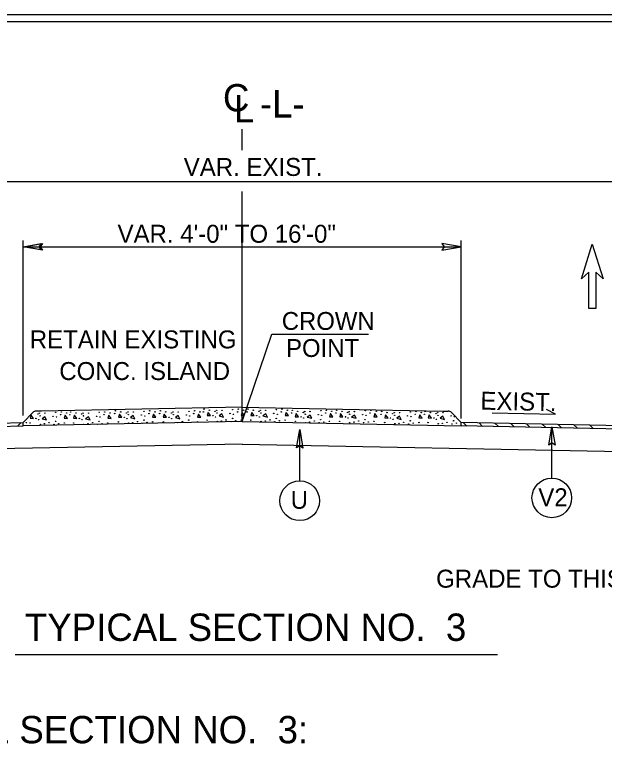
# Model space of a CAD drawing. Extents: x 1901670 to 1902225, y 193498 to 194278.
# Drawn here: x 1902030.87 to 1902052.41, y 194018.9 to 194045.77 of the extents above; entities that cross this region are included whole.
import ezdxf

# ---------------------------------------------------------------- set-up
doc = ezdxf.new("R2010")
doc.units = 0
for name, color, linetype in [('Old_Level_1', 7, 'Continuous'), ('Old_Level_11', 7, 'Continuous'), ('Old_Level_2', 7, 'Continuous'), ('Old_Level_20', 7, 'Continuous'), ('Prop Dimension', 7, 'Continuous'), ('Sheet Border Standard 30in CELL', 7, 'Continuous'), ('Sheet Plot Border Inside CELL', 7, 'Continuous'), ('Typical Terminator CELL', 7, 'Continuous'), ('Typical Text Grade Point CELL', 7, 'Continuous')]:
    doc.layers.add(name, color=color, linetype=linetype)

# ---------------------------------------------------------------- blocks, each defined once
blk = doc.blocks.new('TERMINATOR')
at = {"layer": 'Typical Terminator CELL'}
blk.add_lwpolyline([(-0.469, 0.081), (0, 0), (-0.471, -0.083), (-0.411, 0)], close=True, dxfattribs=at)

msp = doc.modelspace()

# ---------------------------------------------------------------- linework, layer by layer
at = {"layer": 'Old_Level_1'}
for p, q in [((1902039.184, 194040.822), (1902039.184, 194041.59)), ((1902039.184, 194030.906), (1902039.184, 194039.306)), ((1902039.184, 194031.434), (1902031.851, 194031.288)), ((1902039.184, 194031.434), (1902046.517, 194031.288)), ((1902031.184, 194030.871), (1902031.537, 194031.237)), ((1902031.471, 194031.137), (1902031.437, 194031.024)), ((1902031.557, 194031.017), (1902031.471, 194031.137)), ((1902031.851, 194031.288), (1902031.657, 194031.288)), ((1902032.72, 194031.137), (1902032.686, 194031.024)), ((1902032.807, 194031.017), (1902032.72, 194031.137)), ((1902033.06, 194031.137), (1902033.025, 194031.024)), ((1902033.145, 194031.017), (1902033.06, 194031.137)), ((1902034.308, 194031.137), (1902034.274, 194031.024)), ((1902034.395, 194031.017), (1902034.308, 194031.137)), ((1902034.699, 194031.18), (1902034.665, 194031.066)), ((1902034.784, 194031.06), (1902034.699, 194031.18)), ((1902035.206, 194031.124), (1902035.103, 194031.049)), ((1902035.269, 194031.009), (1902035.206, 194031.124)), ((1902035.948, 194031.18), (1902035.913, 194031.066)), ((1902036.034, 194031.06), (1902035.948, 194031.18)), ((1902036.339, 194031.18), (1902036.304, 194031.066)), ((1902036.424, 194031.06), (1902036.339, 194031.18)), ((1902036.846, 194031.124), (1902036.743, 194031.049)), ((1902036.909, 194031.009), (1902036.846, 194031.124)), ((1902037.588, 194031.18), (1902037.553, 194031.066)), ((1902037.674, 194031.06), (1902037.588, 194031.18)), ((1902037.937, 194031.241), (1902037.903, 194031.127)), ((1902037.903, 194031.127), (1902038.023, 194031.121)), ((1902038.023, 194031.121), (1902037.937, 194031.241)), ((1902038.445, 194031.185), (1902038.342, 194031.11)), ((1902038.507, 194031.07), (1902038.445, 194031.185)), ((1902039.186, 194031.241), (1902039.152, 194031.127)), ((1902039.152, 194031.127), (1902039.273, 194031.121)), ((1902039.273, 194031.121), (1902039.186, 194031.241)), ((1902039.537, 194031.241), (1902039.503, 194031.127)), ((1902039.503, 194031.127), (1902039.623, 194031.121)), ((1902039.623, 194031.121), (1902039.537, 194031.241)), ((1902040.044, 194031.185), (1902039.941, 194031.11)), ((1902040.107, 194031.07), (1902040.044, 194031.185)), ((1902040.786, 194031.241), (1902040.752, 194031.127)), ((1902040.752, 194031.127), (1902040.872, 194031.121)), ((1902040.872, 194031.121), (1902040.786, 194031.241)), ((1902041.159, 194031.198), (1902041.124, 194031.084)), ((1902041.244, 194031.078), (1902041.159, 194031.198)), ((1902041.666, 194031.141), (1902041.563, 194031.066)), ((1902041.729, 194031.027), (1902041.666, 194031.141)), ((1902042.408, 194031.198), (1902042.373, 194031.084)), ((1902042.494, 194031.078), (1902042.408, 194031.198)), ((1902042.781, 194031.198), (1902042.747, 194031.084)), ((1902042.867, 194031.078), (1902042.781, 194031.198)), ((1902043.288, 194031.141), (1902043.185, 194031.066)), ((1902043.351, 194031.027), (1902043.288, 194031.141)), ((1902044.03, 194031.198), (1902043.996, 194031.084)), ((1902044.116, 194031.078), (1902044.03, 194031.198)), ((1902044.427, 194031.155), (1902044.393, 194031.041)), ((1902044.513, 194031.035), (1902044.427, 194031.155)), ((1902045.676, 194031.155), (1902045.642, 194031.041)), ((1902045.763, 194031.035), (1902045.676, 194031.155)), ((1902046.011, 194031.155), (1902045.977, 194031.041)), ((1902046.097, 194031.035), (1902046.011, 194031.155)), ((1902046.517, 194031.288), (1902046.711, 194031.288)), ((1902047.184, 194030.871), (1902046.831, 194031.237)), ((1902048.323, 194031.222), (1902050.638, 194031.173)), ((1902050.638, 194031.173), (1902050.305, 194031.34)), ((1902019.184, 194030.631), (1902031.184, 194030.871)), ((1902030.977, 194030.742), (1902031.105, 194030.869)), ((1902039.184, 194030.906), (1902031.184, 194030.746)), ((1902031.184, 194030.746), (1902031.184, 194030.871)), ((1902031.437, 194031.024), (1902031.557, 194031.017)), ((1902031.979, 194031.081), (1902031.875, 194031.006)), ((1902031.875, 194031.006), (1902032.041, 194030.966)), ((1902032.041, 194030.966), (1902031.979, 194031.081)), ((1902032.686, 194031.024), (1902032.807, 194031.017)), ((1902033.025, 194031.024), (1902033.145, 194031.017)), ((1902033.567, 194031.081), (1902033.464, 194031.006)), ((1902033.464, 194031.006), (1902033.629, 194030.966)), ((1902033.629, 194030.966), (1902033.567, 194031.081)), ((1902034.274, 194031.024), (1902034.395, 194031.017)), ((1902034.665, 194031.066), (1902034.784, 194031.06)), ((1902035.103, 194031.049), (1902035.269, 194031.009)), ((1902035.913, 194031.066), (1902036.034, 194031.06)), ((1902036.304, 194031.066), (1902036.424, 194031.06)), ((1902036.743, 194031.049), (1902036.909, 194031.009)), ((1902037.553, 194031.066), (1902037.674, 194031.06)), ((1902038.342, 194031.11), (1902038.507, 194031.07)), ((1902039.184, 194030.906), (1902047.184, 194030.746)), ((1902039.941, 194031.11), (1902040.107, 194031.07)), ((1902041.124, 194031.084), (1902041.244, 194031.078)), ((1902041.563, 194031.066), (1902041.729, 194031.027)), ((1902042.373, 194031.084), (1902042.494, 194031.078)), ((1902042.747, 194031.084), (1902042.867, 194031.078)), ((1902043.185, 194031.066), (1902043.351, 194031.027)), ((1902043.996, 194031.084), (1902044.116, 194031.078)), ((1902044.393, 194031.041), (1902044.513, 194031.035)), ((1902044.935, 194031.099), (1902044.832, 194031.024)), ((1902044.832, 194031.024), (1902044.997, 194030.984)), ((1902044.997, 194030.984), (1902044.935, 194031.099)), ((1902045.642, 194031.041), (1902045.763, 194031.035)), ((1902045.977, 194031.041), (1902046.097, 194031.035)), ((1902046.519, 194031.099), (1902046.415, 194031.024)), ((1902046.415, 194031.024), (1902046.581, 194030.984)), ((1902046.581, 194030.984), (1902046.519, 194031.099)), ((1902047.184, 194030.746), (1902047.184, 194030.871)), ((1902058.184, 194030.651), (1902047.184, 194030.871)), ((1902047.391, 194030.742), (1902047.264, 194030.869)), ((1902047.968, 194030.73), (1902047.841, 194030.858)), ((1902019.184, 194030.506), (1902031.184, 194030.746)), ((1902057.184, 194030.546), (1902047.184, 194030.746)), ((1902048.546, 194030.719), (1902048.418, 194030.846)), ((1902049.123, 194030.707), (1902048.995, 194030.835)), ((1902049.7, 194030.696), (1902049.572, 194030.823)), ((1902050.277, 194030.684), (1902050.15, 194030.812)), ((1902050.854, 194030.673), (1902050.727, 194030.8)), ((1902051.432, 194030.661), (1902051.304, 194030.789)), ((1902052.009, 194030.649), (1902051.881, 194030.777)), ((1902039.184, 194030.083), (1902015.762, 194029.615)), ((1902039.184, 194030.083), (1902057.184, 194029.723))]:
    msp.add_line(p, q, dxfattribs=at)
for centre in [(1902031.728, 194031.178), (1902031.784, 194031.212), (1902031.801, 194031.115), (1902031.978, 194031.212), (1902032.372, 194031.241), (1902032.549, 194031.155), (1902032.578, 194031.257), (1902032.772, 194031.218), (1902032.888, 194031.155), (1902032.917, 194031.257), (1902033.111, 194031.218), (1902033.316, 194031.178), (1902033.372, 194031.212), (1902033.389, 194031.115), (1902033.566, 194031.212), (1902033.96, 194031.241), (1902034.137, 194031.155), (1902034.166, 194031.257), (1902034.36, 194031.218), (1902034.528, 194031.198), (1902034.556, 194031.299), (1902034.75, 194031.26), (1902034.956, 194031.221), (1902035.012, 194031.255), (1902035.029, 194031.158), (1902035.206, 194031.255), (1902035.503, 194031.141), (1902035.6, 194031.283), (1902035.777, 194031.198), (1902035.805, 194031.299), (1902035.999, 194031.26), (1902036.168, 194031.198), (1902036.196, 194031.299), (1902036.39, 194031.26), (1902036.596, 194031.221), (1902036.652, 194031.255), (1902036.669, 194031.158), (1902036.846, 194031.255), (1902037.143, 194031.141), (1902037.24, 194031.283), (1902037.417, 194031.198), (1902037.445, 194031.299), (1902037.639, 194031.26), (1902037.766, 194031.259), (1902037.795, 194031.36), (1902037.989, 194031.321), (1902038.114, 194031.122), (1902038.194, 194031.281), (1902038.25, 194031.316), (1902038.267, 194031.219), (1902038.444, 194031.316), (1902038.741, 194031.201), (1902038.838, 194031.344), (1902038.867, 194031.173), (1902039.015, 194031.259), (1902039.044, 194031.36), (1902039.238, 194031.321), (1902039.366, 194031.259), (1902039.394, 194031.36), (1902039.589, 194031.321), (1902039.714, 194031.122), (1902039.794, 194031.281), (1902039.85, 194031.316), (1902039.867, 194031.219), (1902040.044, 194031.316), (1902040.341, 194031.201), (1902040.438, 194031.344), (1902040.466, 194031.173), (1902040.615, 194031.259), (1902040.643, 194031.36), (1902040.838, 194031.321), (1902040.988, 194031.215), (1902041.016, 194031.317), (1902041.21, 194031.278), (1902041.416, 194031.238), (1902041.472, 194031.272), (1902041.489, 194031.175), (1902041.666, 194031.272), (1902041.963, 194031.158), (1902042.06, 194031.301), (1902042.088, 194031.13), (1902042.237, 194031.215), (1902042.265, 194031.317), (1902042.459, 194031.278), (1902042.61, 194031.215), (1902042.638, 194031.317), (1902042.833, 194031.278), (1902043.038, 194031.238), (1902043.094, 194031.272), (1902043.111, 194031.175), (1902043.288, 194031.272), (1902043.585, 194031.158), (1902043.682, 194031.301), (1902043.71, 194031.13), (1902043.859, 194031.215), (1902043.887, 194031.317), (1902044.082, 194031.278), (1902044.256, 194031.173), (1902044.285, 194031.274), (1902044.479, 194031.235), (1902044.684, 194031.195), (1902044.74, 194031.23), (1902044.757, 194031.133), (1902044.934, 194031.23), (1902045.231, 194031.115), (1902045.328, 194031.258), (1902045.505, 194031.173), (1902045.534, 194031.274), (1902045.728, 194031.235), (1902045.84, 194031.173), (1902045.869, 194031.274), (1902046.063, 194031.235), (1902046.268, 194031.195), (1902046.324, 194031.23), (1902046.341, 194031.133), (1902046.518, 194031.23), (1902046.815, 194031.115), (1902031.303, 194030.869), (1902031.437, 194030.852), (1902031.648, 194031.018), (1902031.744, 194030.972), (1902032.132, 194030.864), (1902032.275, 194031.098), (1902032.366, 194030.915), (1902032.401, 194031.069), (1902032.686, 194030.852), (1902033.025, 194030.852), (1902033.236, 194031.018), (1902033.332, 194030.972), (1902033.721, 194030.864), (1902033.863, 194031.098), (1902033.955, 194030.915), (1902033.989, 194031.069), (1902034.274, 194030.852), (1902034.665, 194030.895), (1902034.876, 194031.061), (1902034.972, 194031.015), (1902035.035, 194030.849), (1902035.189, 194030.867), (1902035.36, 194030.907), (1902035.594, 194030.958), (1902035.628, 194031.112), (1902035.708, 194030.872), (1902035.914, 194030.895), (1902036.305, 194030.895), (1902036.516, 194031.061), (1902036.612, 194031.015), (1902036.829, 194030.867), (1902037, 194030.907), (1902037.234, 194030.958), (1902037.268, 194031.112), (1902037.554, 194030.895), (1902037.903, 194030.956), (1902038.21, 194031.076), (1902038.273, 194030.91), (1902038.427, 194030.927), (1902038.598, 194030.967), (1902038.775, 194030.905), (1902038.833, 194031.019), (1902038.947, 194030.933), (1902039.152, 194030.956), (1902039.503, 194030.956), (1902039.81, 194031.076), (1902039.873, 194030.91), (1902040.027, 194030.927), (1902040.198, 194030.967), (1902040.375, 194030.905), (1902040.432, 194031.019), (1902040.546, 194030.933), (1902040.752, 194030.956), (1902041.125, 194030.913), (1902041.336, 194031.078), (1902041.432, 194031.033), (1902041.495, 194030.867), (1902041.649, 194030.884), (1902041.82, 194030.924), (1902041.997, 194030.861), (1902042.054, 194030.976), (1902042.168, 194030.89), (1902042.374, 194030.913), (1902042.747, 194030.913), (1902042.958, 194031.078), (1902043.054, 194031.033), (1902043.117, 194030.867), (1902043.271, 194030.884), (1902043.442, 194030.924), (1902043.619, 194030.861), (1902043.676, 194030.976), (1902043.79, 194030.89), (1902043.996, 194030.913), (1902044.393, 194030.87), (1902044.604, 194031.036), (1902044.7, 194030.99), (1902045.089, 194030.881), (1902045.323, 194030.933), (1902045.357, 194031.087), (1902045.437, 194030.847), (1902045.642, 194030.87), (1902045.977, 194030.87), (1902046.188, 194031.036), (1902046.284, 194030.99), (1902046.672, 194030.881), (1902046.907, 194030.933), (1902046.941, 194031.087), (1902047.021, 194030.847), (1902031.807, 194030.807), (1902031.961, 194030.824), (1902032.309, 194030.801), (1902032.481, 194030.83), (1902033.395, 194030.807), (1902033.549, 194030.824), (1902033.897, 194030.801), (1902034.069, 194030.83), (1902035.537, 194030.844), (1902044.763, 194030.824), (1902044.917, 194030.842), (1902045.265, 194030.819), (1902046.347, 194030.824), (1902046.501, 194030.842), (1902046.849, 194030.819)]:
    msp.add_circle(centre, 0.00802, dxfattribs=at)
for centre, start, end in [((1902031.657, 194031.121), 90, 135.9991), ((1902046.711, 194031.121), 44.0009, 90)]:
    msp.add_arc(centre, 0.167, start, end, dxfattribs=at)
at = {"layer": 'Old_Level_11'}
for p, q in [((1902041.287, 194028.737), (1902041.287, 194030.612)), ((1902050.498, 194028.843), (1902050.498, 194030.717)), ((1902030.892, 194022.398), (1902047.518, 194022.398)), ((1902031.892, 194022.398), (1902048.518, 194022.398))]:
    msp.add_line(p, q, dxfattribs=at)
for points in [[(1902041.172, 194029.94), (1902041.287, 194030.612), (1902041.407, 194029.936), (1902041.287, 194030.022)], [(1902050.383, 194030.045), (1902050.498, 194030.717), (1902050.618, 194030.042), (1902050.498, 194030.127)]]:
    msp.add_lwpolyline(points, close=True, dxfattribs=at)
for centre in [(1902041.287, 194028.012), (1902050.498, 194028.117)]:
    msp.add_circle(centre, 0.725, dxfattribs=at)
at = {"layer": 'Prop Dimension'}
for p, q in [((1902019.184, 194039.681), (1902033.184, 194039.681)), ((1902033.184, 194039.681), (1902045.184, 194039.681)), ((1902045.184, 194039.681), (1902059.184, 194039.681)), ((1902031.184, 194031.129), (1902031.184, 194037.518)), ((1902047.184, 194031.014), (1902047.184, 194037.518)), ((1902031.184, 194037.291), (1902047.184, 194037.291))]:
    msp.add_line(p, q, dxfattribs=at)
msp.add_lwpolyline([(1902052.371, 194036.116), (1902052.1, 194036.366), (1902052.1, 194035.032), (1902051.85, 194035.032), (1902051.85, 194036.366), (1902051.58, 194036.116), (1902051.975, 194037.386)], close=True, dxfattribs=at)
msp.add_lwpolyline([(1902052.371, 194036.116), (1902052.1, 194036.366), (1902052.1, 194035.032), (1902051.85, 194035.032), (1902051.85, 194036.366), (1902051.58, 194036.116), (1902051.975, 194037.386)], close=True, dxfattribs=at)
at = {"layer": 'Sheet Border Standard 30in CELL'}
msp.add_lwpolyline([(1902132.544, 194045.514), (1901982.544, 194045.514), (1901982.544, 193940.514), (1902132.544, 193940.514)], close=True, dxfattribs=at)
at = {"layer": 'Sheet Plot Border Inside CELL'}
msp.add_lwpolyline([(1902133.794, 194045.769), (1901967.144, 194045.769), (1901967.144, 193940.259), (1902133.794, 193940.259)], close=True, dxfattribs=at)
at = {"layer": 'Typical Text Grade Point CELL'}
for p, q in [((1902039.184, 194030.906), (1902040.268, 194034.099)), ((1902040.268, 194034.099), (1902043.806, 194034.099))]:
    msp.add_line(p, q, dxfattribs=at)

# ---------------------------------------------------------------- block references
at = {"layer": 'Prop Dimension', "rotation": 180}
for p, xscale, yscale in [((1902031.184, 194037.291), 1.5, 1.5), ((1902031.184, 194037.292), 1.4025053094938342, 1.4025053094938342)]:
    msp.add_blockref('TERMINATOR', p, dxfattribs=dict(at, xscale=xscale, yscale=yscale))
at = {"layer": 'Prop Dimension', "xscale": 1.5, "yscale": -1.5}
msp.add_blockref('TERMINATOR', (1902047.184, 194037.291), dxfattribs=at)

# ---------------------------------------------------------------- texts
at = {"layer": 'Old_Level_1'}
msp.add_text('GRADE TO THIS LINE', height=0.656, dxfattribs=at).set_placement((1902046.271, 194024.837))
at = {"layer": 'Old_Level_11'}
for s, p in [('TYPICAL SECTION NO.  3', (1902031.248, 194022.892)), ('USE TYPICAL SECTION NO.  3:', (1902021.978, 194019.15))]:
    msp.add_text(s, height=1, dxfattribs=at).set_placement(p)
at = {"layer": 'Old_Level_2'}
for s, height, p in [('C', 1, (1902038.482, 194042.236)), ('RETAIN EXISTING', 0.65596, (1902031.424, 194033.579)), ('CONC. ISLAND', 0.65596, (1902032.503, 194032.423))]:
    msp.add_text(s, height=height, dxfattribs=at).set_placement(p)
for s, height, rotation, p in [('-L-', 1, 359.9469, (1902039.833, 194042.014)), ('L', 1, 359.9469, (1902038.884, 194041.832)), ('EXIST.', 0.656, 358.8084, (1902047.884, 194031.342))]:
    msp.add_text(s, height=height, rotation=rotation, dxfattribs=at).set_placement(p)
at = {"layer": 'Old_Level_20'}
for s, height, p in [('V2', 0.656, (1902050.004, 194027.811)), ('U', 0.649, (1902040.96, 194027.719))]:
    msp.add_text(s, height=height, dxfattribs=at).set_placement(p)
at = {"layer": 'Prop Dimension'}
for s, p in [('VAR. EXIST.', (1902037.051, 194039.879)), ('VAR. 4\'-0" TO 16\'-0"', (1902034.632, 194037.438))]:
    msp.add_text(s, height=0.656, dxfattribs=at).set_placement(p)
at = {"layer": 'Typical Text Grade Point CELL'}
for s, p in [('CROWN', (1902040.632, 194034.255)), ('POINT', (1902040.789, 194033.266))]:
    msp.add_text(s, height=0.6525, dxfattribs=at).set_placement(p)

doc.saveas('drawing.dxf')
